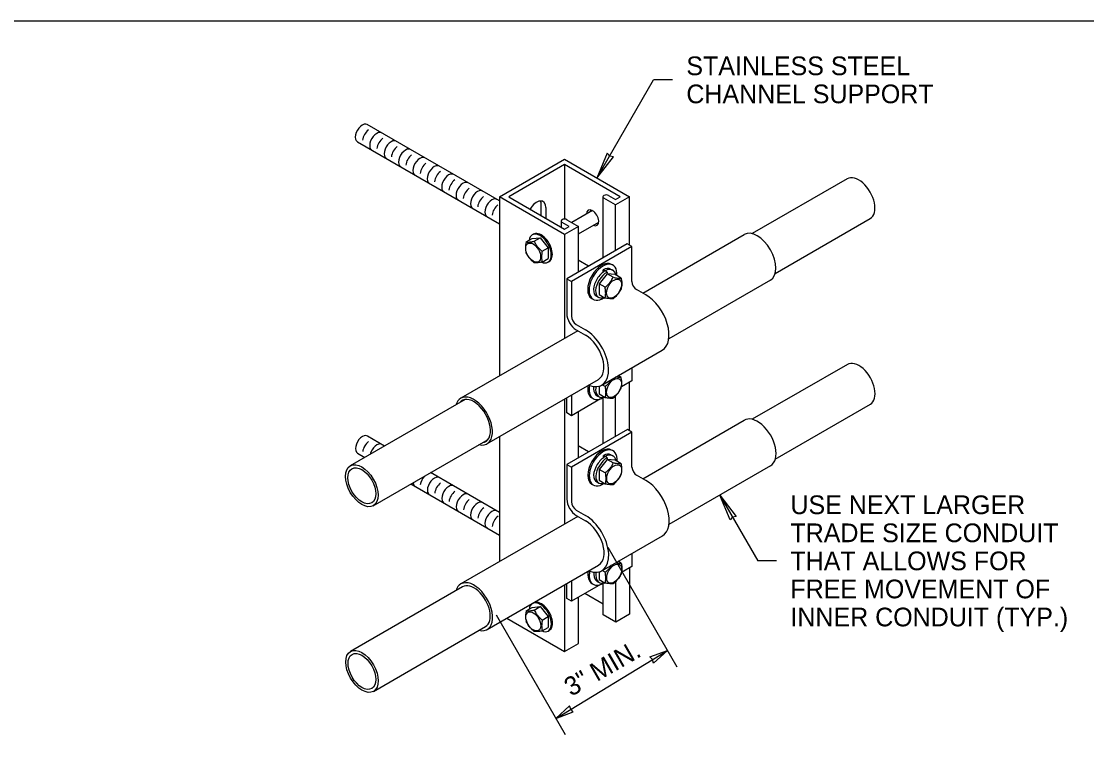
# Model space of a CAD drawing. Extents: x 99862 to 103151, y 100000 to 102076.
# Drawn here: x 101434 to 102346, y 101455 to 102076 of the extents above; entities that cross this region are included whole.
import ezdxf

# ---------------------------------------------------------------- set-up
doc = ezdxf.new("R2010")
doc.units = 0
for name, color, linetype in [('Level 1', 7, 'Continuous'), ('Level 15', 7, 'Continuous'), ('Level 2', 7, 'Continuous'), ('Level 20', 7, 'Continuous'), ('Level 4', 7, 'Continuous'), ('Level 5', 7, 'Continuous'), ('Level 6', 7, 'Continuous'), ('Level 8', 7, 'Continuous'), ('Level 9', 7, 'Continuous')]:
    doc.layers.add(name, color=color, linetype=linetype)

msp = doc.modelspace()

# ---------------------------------------------------------------- linework, layer by layer
at = {"layer": 'Level 1'}
for p, q in [((101843.6, 101925.34), (101899.28, 101957.49)), ((101899.28, 101952.9), (101851.55, 101925.34)), ((101899.28, 101957.49), (101954.97, 101925.34)), ((101899.28, 101952.9), (101899.28, 101906.3)), ((101947.01, 101925.34), (101899.28, 101952.9)), ((101899.28, 101893.19), (101843.6, 101925.34)), ((101843.6, 101925.34), (101843.6, 101772.2)), ((101851.55, 101925.34), (101899.28, 101897.79)), ((101932.26, 101925.34), (101932.26, 101873.19)), ((101943.03, 101918.45), (101933.07, 101924.2)), ((101937.05, 101926.5), (101943.03, 101923.05)), ((101954.97, 101925.34), (101943.03, 101918.45)), ((101943.03, 101923.05), (101947.01, 101925.34)), ((101954.97, 101884.01), (101954.97, 101925.34)), ((101879.39, 101909.27), (101879.39, 101918.45)), ((101883.37, 101916.16), (101883.37, 101906.97)), ((101943.03, 101879.41), (101943.03, 101918.45)), ((101896.46, 101904.68), (101896.46, 101899.42)), ((101901.25, 101905.83), (101911.21, 101900.08)), ((101903.26, 101900.08), (101897.28, 101903.54)), ((101911.21, 101900.08), (101899.28, 101893.19)), ((101899.28, 101897.79), (101903.26, 101900.08)), ((101911.21, 101861.04), (101911.21, 101900.08)), ((101899.28, 101893.19), (101899.28, 101804.35)), ((101954.97, 101725.27), (101954.97, 101766.89)), ((101899.28, 101752.39), (101899.28, 101645.46)), ((101932.26, 101753.55), (101932.26, 101714.3)), ((101943.03, 101720.52), (101943.03, 101755.13)), ((101911.21, 101702.15), (101911.21, 101741.63)), ((101843.73, 101720.32), (101843.73, 101613.39)), ((101955.09, 101608.08), (101955.09, 101568.5)), ((101932.39, 101567.84), (101932.39, 101594.78)), ((101943.16, 101561.61), (101943.16, 101596.31)), ((101899.41, 101593.58), (101899.41, 101536.35)), ((101932.39, 101577.02), (101916.85, 101585.99)), ((101911.34, 101543.24), (101911.34, 101582.81)), ((101943.16, 101561.61), (101932.39, 101567.84)), ((101955.09, 101568.5), (101943.16, 101561.61)), ((101849.85, 101564.96), (101899.41, 101536.35)), ((101899.41, 101536.35), (101911.34, 101543.24))]:
    msp.add_line(p, q, dxfattribs=at)
msp.add_lwpolyline([(99862, 99999.5), (103151, 99999.5), (103151, 102075.5), (99862, 102075.5)], close=True, dxfattribs=at)
for centre, major_axis, start_param, end_param in [((101935.05, 101925.34), (-2.79, 0), 5.497787, 7.068583), ((101935.08, 101925.36), (-2.79, 0), 3.926991, 5.497787), ((101875.42, 101911.56), (5.63, 9.74), 5.497787, 7.853982), ((101871.44, 101913.86), (-5.63, -9.74), 2.356194, 2.780226), ((101923.37, 101907.4), (3.73, -6.46), 5.605091, 10.177712), ((101926.89, 101909.43), (-3.73, 6.46), 0.490883, 0.752934), ((101899.25, 101904.68), (-2.79, 0), 5.497787, 7.068583), ((101899.28, 101904.69), (-2.79, 0), 3.926991, 5.497787), ((101926.89, 101909.43), (-3.73, 6.46), 2.463499, 2.65071)]:
    msp.add_ellipse(centre, major_axis=major_axis, ratio=0.57735, start_param=start_param, end_param=end_param, dxfattribs=at)
at = {"layer": 'Level 15'}
for p, q in [((101927.12, 101941.42), (101975.62, 102025.42)), ((101991.62, 102025.42), (101975.62, 102025.42)), ((102032.21, 101670.25), (102064.71, 101613.96)), ((102080.71, 101613.96), (102064.71, 101613.96)), ((101891.8, 101479.28), (101987.37, 101537.32))]:
    msp.add_line(p, q, dxfattribs=at)
for points in [[(101927.12, 101941.42), (101941.12, 101959.7), (101938.01, 101960.27), (101935.95, 101962.68)], [(102032.21, 101670.25), (102046.21, 101651.97), (102043.1, 101651.4), (102041.04, 101648.99)], [(101987.37, 101537.32), (101975.53, 101526.52), (101974.55, 101529.53), (101972.33, 101531.79)], [(101891.8, 101479.28), (101906.84, 101484.8), (101904.61, 101487.06), (101903.64, 101490.08)]]:
    msp.add_lwpolyline(points, close=True, dxfattribs=at)
at = {"layer": 'Level 2'}
for p, q in [((101952.98, 101885.15), (101901.27, 101855.3)), ((101956.96, 101882.86), (101905.25, 101853)), ((101956.96, 101882.86), (101952.98, 101885.15)), ((101956.96, 101853), (101956.96, 101882.86)), ((101901.27, 101855.3), (101905.25, 101853)), ((101901.27, 101855.3), (101901.27, 101825.45)), ((101905.25, 101853), (101905.25, 101823.15)), ((101968.89, 101841.52), (101960.93, 101846.12)), ((101909.23, 101816.26), (101917.18, 101811.67)), ((101909.23, 101811.67), (101917.18, 101807.08)), ((101931.24, 101764.35), (101982.95, 101794.2)), ((101956.96, 101779.19), (101956.96, 101768.04)), ((101956.96, 101768.04), (101948.02, 101762.88)), ((101901.27, 101740.48), (101901.27, 101753.54)), ((101905.25, 101755.84), (101905.25, 101738.18)), ((101930.13, 101752.55), (101905.25, 101738.18)), ((101905.25, 101738.18), (101901.27, 101740.48)), ((101953.11, 101726.34), (101901.4, 101696.49)), ((101957.08, 101724.04), (101905.38, 101694.19)), ((101957.08, 101724.04), (101953.11, 101726.34)), ((101957.08, 101694.19), (101957.08, 101724.04)), ((101901.4, 101696.49), (101905.38, 101694.19)), ((101901.4, 101696.49), (101901.4, 101666.63)), ((101905.38, 101694.19), (101905.38, 101664.34)), ((101969.02, 101682.71), (101961.06, 101687.3)), ((101909.35, 101657.45), (101917.31, 101652.86)), ((101909.35, 101652.86), (101917.31, 101648.26)), ((101931.37, 101605.53), (101983.08, 101635.39)), ((101957.08, 101620.38), (101957.08, 101609.22)), ((101957.08, 101609.22), (101948.15, 101604.07)), ((101901.4, 101581.67), (101901.4, 101594.72)), ((101905.38, 101597.02), (101905.38, 101579.37)), ((101930.26, 101593.74), (101905.38, 101579.37)), ((101905.38, 101579.37), (101901.4, 101581.67))]:
    msp.add_line(p, q, dxfattribs=at)
for centre, major_axis, start_param, end_param in [((101960.93, 101850.71), (-2.81, 4.87), 0.785398, 2.356194), ((101968.89, 101818.56), (14.06, -24.36), 6.283185, 8.63938), ((101909.23, 101820.86), (-5.62, 9.74), 0.785398, 2.356194), ((101909.23, 101820.86), (-2.81, 4.87), 0.785398, 2.356194), ((101917.18, 101788.71), (14.06, -24.36), 5.639684, 8.63938), ((101917.18, 101788.71), (11.25, -19.49), 0, 2.356194), ((101961.06, 101691.89), (-2.81, 4.87), 0.785398, 2.356194), ((101969.02, 101659.74), (14.06, -24.36), 0, 2.356194), ((101909.35, 101662.04), (-5.62, 9.74), 0.785398, 2.356194), ((101909.35, 101662.04), (-2.81, 4.87), 0.785398, 2.356194), ((101917.31, 101629.89), (14.06, -24.36), 5.639684, 8.63938), ((101917.31, 101629.89), (11.25, -19.49), 6.283185, 8.63938)]:
    msp.add_ellipse(centre, major_axis=major_axis, ratio=0.57735, start_param=start_param, end_param=end_param, dxfattribs=at)
at = {"layer": 'Level 20'}
for p, q in [((101936.29, 101625.78), (101995.37, 101523.46)), ((101840.71, 101567.74), (101899.8, 101465.42))]:
    msp.add_line(p, q, dxfattribs=at)
at = {"layer": 'Level 4'}
for p, q in [((101923.2, 101913.59), (101905.51, 101903.37)), ((101911.21, 101893.68), (101928.61, 101903.72)), ((101866.44, 101886.75), (101871.55, 101889.71)), ((101871.55, 101889.71), (101878.44, 101890.32)), ((101873.33, 101887.37), (101878.44, 101890.32)), ((101878.44, 101890.32), (101885.33, 101881.75)), ((101880.22, 101878.8), (101885.33, 101881.75)), ((101885.33, 101881.75), (101885.33, 101872.57)), ((101880.22, 101869.61), (101885.33, 101872.57)), ((101919.82, 101866.01), (101911, 101871.11)), ((101935.76, 101859.5), (101928.87, 101850.93)), ((101940.88, 101856.55), (101935.76, 101859.5)), ((101942.65, 101858.88), (101935.76, 101859.5)), ((101947.76, 101855.93), (101942.65, 101858.88)), ((101933.99, 101847.98), (101928.87, 101850.93)), ((101928.87, 101850.93), (101928.87, 101841.74)), ((101928.87, 101841.74), (101933.99, 101838.79)), ((101947.76, 101770.97), (101945.23, 101772.43)), ((101928.87, 101763.38), (101928.87, 101756.78)), ((101933.99, 101763.01), (101931.46, 101764.47)), ((101928.87, 101756.78), (101933.99, 101753.82)), ((101919.95, 101707.2), (101911.13, 101712.29)), ((101935.89, 101700.69), (101929, 101692.12)), ((101941, 101697.73), (101935.89, 101700.69)), ((101942.78, 101700.07), (101935.89, 101700.69)), ((101947.89, 101697.12), (101942.78, 101700.07)), ((101934.11, 101689.16), (101929, 101692.12)), ((101929, 101692.12), (101929, 101682.93)), ((101929, 101682.93), (101934.11, 101679.98)), ((101947.89, 101612.15), (101945.36, 101613.61)), ((101929, 101604.56), (101929, 101597.96)), ((101934.11, 101604.2), (101931.58, 101605.66)), ((101929, 101597.96), (101934.11, 101595.01)), ((101866.57, 101571.27), (101871.68, 101574.23)), ((101871.68, 101574.23), (101878.57, 101574.84)), ((101873.46, 101571.89), (101878.57, 101574.84)), ((101878.57, 101574.84), (101885.46, 101566.27)), ((101880.34, 101563.32), (101885.46, 101566.27)), ((101885.46, 101566.27), (101885.46, 101557.08)), ((101880.34, 101554.13), (101885.46, 101557.08))]:
    msp.add_line(p, q, dxfattribs=at)
for centre, major_axis in [((101872.47, 101877.69), (4.5, -7.79)), ((101941.73, 101846.87), (4.5, 7.79)), ((101941.73, 101761.9), (4.5, 7.79)), ((101941.86, 101688.06), (4.5, 7.79)), ((101941.86, 101603.09), (4.5, 7.79)), ((101872.6, 101562.21), (4.5, -7.79))]:
    msp.add_ellipse(centre, major_axis=major_axis, ratio=0.57735, dxfattribs=at)
for points in [[(101866.44, 101886.75), (101866.26, 101885.9), (101866.12, 101885.05), (101865.92, 101883.41), (101865.87, 101882.6), (101865.87, 101881.05), (101865.92, 101880.3), (101866.12, 101878.88), (101866.27, 101878.21), (101866.44, 101877.57)], [(101866.44, 101886.75), (101867.22, 101886.65), (101868.14, 101886.63), (101869.89, 101886.78), (101870.53, 101886.87), (101871.88, 101887.08), (101872.59, 101887.22), (101873.33, 101887.37)], [(101873.33, 101887.37), (101874.11, 101885.77), (101875.03, 101884.22), (101876.78, 101882.03), (101877.42, 101881.34), (101878.77, 101880.03), (101879.48, 101879.4), (101880.22, 101878.8)], [(101873.33, 101869), (101871.85, 101870.2), (101870.49, 101871.49), (101868.73, 101873.68), (101868.2, 101874.43), (101867.25, 101875.98), (101866.83, 101876.77), (101866.44, 101877.57)], [(101880.22, 101878.8), (101880.04, 101877.95), (101879.9, 101877.1), (101879.7, 101875.45), (101879.65, 101874.65), (101879.65, 101873.1), (101879.7, 101872.34), (101879.9, 101870.93), (101880.04, 101870.26), (101880.22, 101869.61)], [(101880.22, 101869.61), (101878.74, 101869.31), (101877.38, 101869.08), (101875.62, 101868.92), (101875.09, 101868.9), (101874.14, 101868.92), (101873.72, 101868.95), (101873.33, 101869)], [(101933.99, 101847.98), (101935.46, 101849.18), (101936.83, 101850.47), (101939.17, 101853.38), (101940.1, 101854.94), (101940.88, 101856.55)], [(101940.88, 101856.55), (101942.35, 101856.25), (101943.72, 101856.02), (101946.06, 101855.81), (101946.98, 101855.83), (101947.76, 101855.93)], [(101947.76, 101855.93), (101947.94, 101855.08), (101948.08, 101854.23), (101948.28, 101852.58), (101948.34, 101851.78), (101948.33, 101850.23), (101948.28, 101849.48), (101948.08, 101848.06), (101947.94, 101847.39), (101947.76, 101846.75)], [(101933.99, 101838.79), (101934.16, 101839.44), (101934.3, 101840.11), (101934.5, 101841.52), (101934.56, 101842.27), (101934.56, 101843.83), (101934.5, 101844.63), (101934.31, 101846.28), (101934.16, 101847.13), (101933.99, 101847.98)], [(101947.76, 101846.75), (101946.99, 101845.14), (101946.06, 101843.59), (101943.73, 101840.68), (101942.35, 101839.38), (101940.88, 101838.18)], [(101940.88, 101838.18), (101940.1, 101838.08), (101939.17, 101838.05), (101936.84, 101838.26), (101935.46, 101838.49), (101933.99, 101838.79)], [(101939.53, 101769.14), (101939.07, 101768.4), (101938.57, 101767.67), (101936.84, 101765.52), (101935.46, 101764.21), (101933.99, 101763.01)], [(101947.76, 101770.97), (101946.99, 101770.86), (101946.06, 101770.84), (101944.33, 101770.99), (101943.72, 101771.07), (101943.07, 101771.18)], [(101947.76, 101761.78), (101947.94, 101762.43), (101948.08, 101763.11), (101948.28, 101764.53), (101948.34, 101765.27), (101948.33, 101766.82), (101948.28, 101767.64), (101948.08, 101769.29), (101947.94, 101770.12), (101947.76, 101770.97)], [(101933.99, 101763.01), (101934.16, 101762.17), (101934.3, 101761.33), (101934.5, 101759.69), (101934.56, 101758.87), (101934.56, 101757.32), (101934.5, 101756.58), (101934.31, 101755.16), (101934.16, 101754.48), (101933.99, 101753.82)], [(101940.88, 101753.21), (101942.35, 101754.41), (101943.72, 101755.71), (101946.06, 101758.61), (101946.98, 101760.17), (101947.76, 101761.78)], [(101933.99, 101753.82), (101935.46, 101753.52), (101936.83, 101753.29), (101939.17, 101753.08), (101940.1, 101753.11), (101940.88, 101753.21)], [(101941, 101697.73), (101940.22, 101696.13), (101939.29, 101694.57), (101936.96, 101691.66), (101935.59, 101690.36), (101934.11, 101689.16)], [(101947.89, 101697.12), (101947.11, 101697.02), (101946.18, 101696.99), (101943.84, 101697.2), (101942.48, 101697.43), (101941, 101697.73)], [(101947.89, 101687.93), (101948.07, 101688.58), (101948.21, 101689.25), (101948.41, 101690.66), (101948.46, 101691.41), (101948.46, 101692.97), (101948.41, 101693.77), (101948.21, 101695.42), (101948.07, 101696.27), (101947.89, 101697.12)], [(101934.11, 101689.16), (101934.29, 101688.31), (101934.43, 101687.46), (101934.63, 101685.81), (101934.69, 101685.01), (101934.69, 101683.46), (101934.63, 101682.71), (101934.43, 101681.29), (101934.29, 101680.62), (101934.11, 101679.98)], [(101941, 101679.36), (101942.48, 101680.56), (101943.86, 101681.87), (101946.19, 101684.78), (101947.11, 101686.33), (101947.89, 101687.93)], [(101934.11, 101679.98), (101935.59, 101679.67), (101936.97, 101679.44), (101939.3, 101679.24), (101940.22, 101679.26), (101941, 101679.36)], [(101934.11, 101604.2), (101935.59, 101605.4), (101936.97, 101606.7), (101938.7, 101608.86), (101939.2, 101609.58), (101939.66, 101610.32)], [(101934.11, 101595.01), (101934.29, 101595.66), (101934.43, 101596.34), (101934.63, 101597.76), (101934.69, 101598.5), (101934.69, 101600.05), (101934.63, 101600.87), (101934.43, 101602.52), (101934.29, 101603.35), (101934.11, 101604.2)], [(101943.2, 101612.36), (101943.85, 101612.26), (101944.46, 101612.18), (101946.19, 101612.02), (101947.11, 101612.05), (101947.89, 101612.15)], [(101947.89, 101612.15), (101948.07, 101611.31), (101948.21, 101610.47), (101948.41, 101608.83), (101948.46, 101608.01), (101948.46, 101606.46), (101948.41, 101605.72), (101948.21, 101604.3), (101948.07, 101603.62), (101947.89, 101602.97)], [(101941, 101594.4), (101940.22, 101594.29), (101939.29, 101594.27), (101936.96, 101594.48), (101935.59, 101594.71), (101934.11, 101595.01)], [(101947.89, 101602.97), (101947.11, 101601.36), (101946.18, 101599.8), (101943.84, 101596.89), (101942.48, 101595.6), (101941, 101594.4)], [(101866.57, 101571.27), (101866.39, 101570.42), (101866.25, 101569.57), (101866.05, 101567.92), (101865.99, 101567.12), (101866, 101565.57), (101866.05, 101564.82), (101866.25, 101563.4), (101866.39, 101562.73), (101866.57, 101562.09)], [(101866.57, 101571.27), (101867.34, 101571.17), (101868.27, 101571.15), (101870.02, 101571.3), (101870.66, 101571.39), (101872, 101571.6), (101872.72, 101571.74), (101873.46, 101571.89)], [(101873.46, 101571.89), (101874.23, 101570.28), (101875.16, 101568.73), (101876.91, 101566.55), (101877.55, 101565.86), (101878.89, 101564.54), (101879.61, 101563.92), (101880.34, 101563.32)], [(101873.46, 101553.52), (101871.98, 101554.72), (101870.61, 101556.01), (101868.86, 101558.19), (101868.33, 101558.95), (101867.38, 101560.49), (101866.96, 101561.28), (101866.57, 101562.09)], [(101880.34, 101563.32), (101880.17, 101562.47), (101880.02, 101561.62), (101879.83, 101559.97), (101879.77, 101559.17), (101879.77, 101557.61), (101879.83, 101556.86), (101880.03, 101555.45), (101880.17, 101554.78), (101880.34, 101554.13)], [(101880.34, 101554.13), (101878.87, 101553.83), (101877.5, 101553.6), (101875.75, 101553.44), (101875.22, 101553.42), (101874.27, 101553.43), (101873.84, 101553.47), (101873.46, 101553.52)]]:
    msp.add_open_spline(points, degree=3, dxfattribs=at)
at = {"layer": 'Level 5'}
for p, q in [((101872.65, 101893.38), (101871.69, 101892.83)), ((101885.19, 101869.45), (101886.14, 101870)), ((101940.73, 101866.93), (101939.54, 101867.62)), ((101922.66, 101838.39), (101923.86, 101837.7)), ((101922.66, 101753.42), (101923.86, 101752.74)), ((101940.86, 101708.12), (101939.67, 101708.8)), ((101922.79, 101679.58), (101923.98, 101678.89)), ((101922.79, 101594.61), (101923.98, 101593.92)), ((101872.77, 101577.9), (101871.82, 101577.35)), ((101885.32, 101553.96), (101886.27, 101554.51))]:
    msp.add_line(p, q, dxfattribs=at)
for centre, major_axis, start_param, end_param in [((101878.44, 101881.14), (6.75, -11.69), 6.283185, 10.060003), ((101879.39, 101881.69), (6.75, -11.69), 6.283185, 9.42479), ((101878.44, 101881.14), (6.75, -11.69), 5.62548, 6.283185), ((101931.1, 101853), (8.44, 14.61), 0.000006, 3.141593), ((101932.29, 101852.32), (8.44, 14.61), 5.41204, 10.295924), ((101931.1, 101768.04), (8.44, 14.61), 2.157168, 3.141593), ((101932.29, 101767.35), (8.44, 14.61), 2.10764, 3.932392), ((101931.23, 101694.19), (8.44, 14.61), 0.000006, 3.141593), ((101932.42, 101693.5), (8.44, 14.61), 5.41204, 10.295924), ((101931.23, 101609.22), (8.44, 14.61), 2.157168, 3.141593), ((101932.42, 101608.54), (8.44, 14.61), 2.10764, 3.923919), ((101878.57, 101565.66), (6.75, -11.69), 6.283185, 10.060003), ((101879.52, 101566.21), (6.75, -11.69), 6.283185, 9.42479), ((101878.57, 101565.66), (6.75, -11.69), 5.62548, 6.283185)]:
    msp.add_ellipse(centre, major_axis=major_axis, ratio=0.57735, start_param=start_param, end_param=end_param, dxfattribs=at)
at = {"layer": 'Level 6'}
for p, q in [((101932.55, 101861.05), (101932.48, 101863.04)), ((101934.19, 101862.12), (101932.48, 101863.04)), ((101935.71, 101860.92), (101934.02, 101862.01)), ((101934.2, 101861.89), (101934.19, 101862.12)), ((101935.71, 101860.92), (101935.63, 101859.34)), ((101938.82, 101863.61), (101940.54, 101862.7)), ((101926.87, 101840.27), (101928.67, 101839.33)), ((101929.21, 101754.12), (101927.51, 101755)), ((101932.67, 101702.24), (101932.61, 101704.22)), ((101934.32, 101703.31), (101932.61, 101704.22)), ((101938.95, 101704.8), (101940.66, 101703.88)), ((101935.84, 101702.11), (101934.15, 101703.2)), ((101934.33, 101703.08), (101934.32, 101703.31)), ((101935.84, 101702.11), (101935.76, 101700.53)), ((101926.99, 101681.45), (101928.8, 101680.52)), ((101929.34, 101595.31), (101927.63, 101596.18))]:
    msp.add_line(p, q, dxfattribs=at)
for centre, major_axis, ratio, start_param, end_param in [((101933.41, 101851.58), (7.08, 11.02), 0.544801, 0.802368, 2.38067), ((101935.2, 101850.55), (7.08, 11.02), 0.544801, 0.811998, 2.370398), ((101932.65, 101852.06), (6.17, 11.55), 0.597856, 6.283185, 7.031394), ((101934.36, 101851.15), (6.17, 11.55), 0.597856, 5.669032, 7.031394), ((101932.88, 101851.9), (-6.02, -11.63), 0.544029, 5.471854, 6.283185), ((101934.68, 101850.96), (-6.02, -11.63), 0.544029, 5.471854, 6.845298), ((101932.96, 101766.81), (-6, -11.64), 0.544801, 5.297068, 5.471187), ((101933.49, 101766.64), (-5.98, -11.65), 0.608892, 5.480166, 6.283185), ((101935.2, 101765.76), (-5.98, -11.65), 0.608892, 5.481165, 6.833013), ((101934.68, 101765.92), (-6, -11.64), 0.544801, 5.227707, 5.471187), ((101932.78, 101693.25), (6.17, 11.55), 0.597856, 6.283185, 7.031394), ((101934.49, 101692.34), (6.17, 11.55), 0.597856, 5.669032, 7.031394), ((101933.54, 101692.77), (7.08, 11.02), 0.544801, 0.802368, 2.38067), ((101935.33, 101691.73), (7.08, 11.02), 0.544801, 0.811998, 2.370398), ((101933.01, 101693.08), (-6.02, -11.63), 0.544029, 5.471854, 6.283185), ((101934.81, 101692.15), (-6.02, -11.63), 0.544029, 5.471854, 6.845298), ((101933.09, 101607.99), (-6, -11.64), 0.544801, 5.297068, 5.471187), ((101934.81, 101607.11), (-6, -11.64), 0.544801, 5.227707, 5.471187), ((101933.62, 101607.83), (-5.98, -11.65), 0.608892, 5.480166, 6.283185), ((101935.33, 101606.95), (-5.98, -11.65), 0.608892, 5.481165, 6.833013)]:
    msp.add_ellipse(centre, major_axis=major_axis, ratio=ratio, start_param=start_param, end_param=end_param, dxfattribs=at)
at = {"layer": 'Level 8'}
for p, q in [((101843.6, 101921.84), (101730.47, 101987.15)), ((101722.03, 101972.54), (101843.6, 101902.35)), ((101745.34, 101712.22), (101730.6, 101720.73)), ((101722.16, 101706.12), (101728.46, 101702.48)), ((101843.73, 101655.42), (101784.71, 101689.49)), ((101767.84, 101679.75), (101843.73, 101635.93))]:
    msp.add_line(p, q, dxfattribs=at)
for centre, start_param, end_param in [((101726.25, 101979.84), 0, 3.141593), ((101732.41, 101976.29), 0.942075, 2.218001), ((101738.57, 101972.73), 0, 3.141593), ((101744.73, 101969.18), 0.942075, 2.218001), ((101750.88, 101965.62), 0, 3.141593), ((101757.04, 101962.07), 0.942075, 2.218001), ((101763.2, 101958.51), 0, 3.141593), ((101769.36, 101954.96), 0.942075, 2.218001), ((101775.52, 101951.4), 0, 3.141593), ((101781.67, 101947.85), 0.942075, 2.218001), ((101787.83, 101944.29), 0, 3.141593), ((101793.99, 101940.74), 0.942075, 2.218001), ((101800.15, 101937.18), 0, 3.141593), ((101806.31, 101933.63), 0.942075, 2.218001), ((101812.46, 101930.07), 0, 3.141593), ((101818.62, 101926.51), 0.942075, 2.218001), ((101824.78, 101922.96), 0, 3.141593), ((101830.94, 101919.4), 0.942075, 2.218001), ((101837.1, 101915.85), 0, 3.141593), ((101843.25, 101912.29), 0.942075, 2.218001), ((101726.38, 101713.43), 0, 3.141593), ((101732.54, 101709.87), 0.942075, 2.218001), ((101738.7, 101706.31), 0, 2.050004), ((101781.8, 101681.43), 1.170703, 2.218001), ((101787.96, 101677.87), 0, 3.141593), ((101775.64, 101684.98), 2.461838, 3.141593), ((101794.12, 101674.32), 0.942075, 2.218001), ((101800.28, 101670.76), 0, 3.141593), ((101787.96, 101677.87), 3.003724, 3.141593), ((101806.43, 101667.21), 0.942075, 2.218001), ((101812.59, 101663.65), 0, 3.141593), ((101818.75, 101660.1), 0.942075, 2.218001), ((101824.91, 101656.54), 0, 3.141593), ((101831.07, 101652.99), 0.942075, 2.218001), ((101837.22, 101649.43), 0, 3.141593), ((101843.38, 101645.88), 0.942075, 2.218001)]:
    msp.add_ellipse(centre, major_axis=(4.22, 7.31), ratio=0.57735, start_param=start_param, end_param=end_param, dxfattribs=at)
at = {"layer": 'Level 9'}
for p, q in [((102141.29, 101940.83), (102059.95, 101893.87)), ((102079.64, 101859.77), (102160.97, 101906.73)), ((101966.27, 101843.03), (102053.1, 101893.16)), ((102075.6, 101854.19), (101988.57, 101803.94)), ((101910.59, 101810.88), (101810.47, 101753.08)), ((102141.41, 101782.01), (102060.08, 101735.05)), ((101832.97, 101714.11), (101928.43, 101769.22)), ((101814.25, 101752.01), (101715.99, 101695.28)), ((102079.77, 101700.95), (102161.1, 101747.91)), ((101966.4, 101684.22), (102053.23, 101734.34)), ((101735.68, 101661.18), (101833.93, 101717.91)), ((102075.73, 101695.37), (101988.7, 101645.13)), ((101910.72, 101652.07), (101810.6, 101594.26)), ((101833.1, 101555.29), (101928.56, 101610.41)), ((101812.01, 101591.83), (101716.12, 101536.47)), ((101735.81, 101502.37), (101831.69, 101557.73))]:
    msp.add_line(p, q, dxfattribs=at)
for centre, major_axis, start_param, end_param in [((102151.13, 101923.78), (9.84, -17.05), 6.28318, 9.424778), ((102064.35, 101873.67), (11.25, -19.49), 0.000006, 3.141593), ((102151.26, 101764.96), (9.84, -17.05), 6.28318, 9.424778), ((101821.72, 101733.59), (-11.25, 19.49), 0, 0.512393), ((101821.72, 101733.59), (-10.13, 17.54), 2.905341, 6.525344), ((101821.72, 101733.59), (-11.25, 19.49), 2.636232, 6.283185), ((102064.48, 101714.86), (11.25, -19.49), 0.000006, 3.175318), ((101821.85, 101574.78), (-11.25, 19.49), 2.636232, 6.283185), ((101821.85, 101574.78), (-11.25, 19.49), 6.283185, 6.788546), ((101821.85, 101574.78), (-9.84, 17.05), 3.14158, 6.283185)]:
    msp.add_ellipse(centre, major_axis=major_axis, ratio=0.57735, start_param=start_param, end_param=end_param, dxfattribs=at)
for centre, major_axis in [((101725.84, 101678.23), (9.84, -17.05)), ((101725.84, 101678.23), (-8.44, 14.61)), ((101725.97, 101519.42), (9.84, -17.05)), ((101725.97, 101519.42), (-8.44, 14.61))]:
    msp.add_ellipse(centre, major_axis=major_axis, ratio=0.57735, dxfattribs=at)

# ---------------------------------------------------------------- texts
at = {"layer": 'Level 20'}
for s, rotation, p in [('STAINLESS STEEL', 360, (102003.62, 102029.42)), ('CHANNEL SUPPORT', 360, (102003.62, 102005.42)), ('3" MIN.', 30.00347, (101905.06, 101497.6))]:
    msp.add_text(s, height=16, rotation=rotation, dxfattribs=at).set_placement(p)
for s, p in [('USE NEXT LARGER ', (102092.71, 101653.96)), ('TRADE SIZE CONDUIT ', (102092.71, 101629.96)), ('THAT ALLOWS FOR ', (102092.71, 101605.96)), ('FREE MOVEMENT OF ', (102092.71, 101581.96)), ('INNER CONDUIT (TYP.)', (102092.71, 101557.96))]:
    msp.add_text(s, height=16, dxfattribs=at).set_placement(p)

doc.saveas('drawing.dxf')
